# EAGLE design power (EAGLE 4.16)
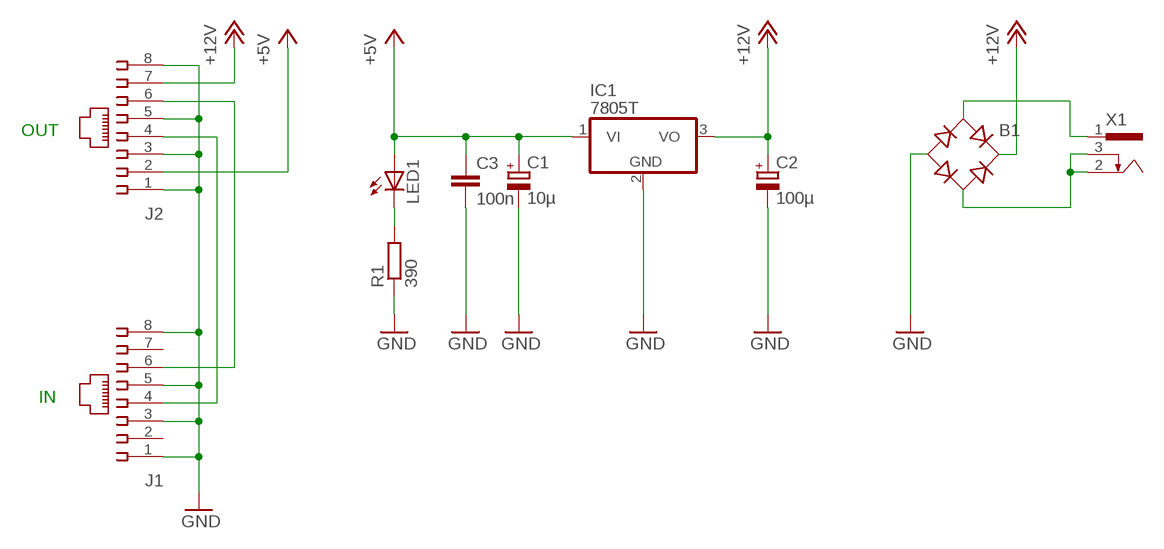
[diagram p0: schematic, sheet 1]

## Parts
B1  RB1A  [RB1A]
C1  10µ  CPOL-EUE2,5-6E  [E2,5-6E]
C2  100µ  CPOL-EUE2,5-6E  [E2,5-6E]
C3  100n  C-EU025-024X044  [C025-024X044]
IC1  7805T  [TO220H]
J1  520243-4  [520243-4]
J2  520243-4  [520243-4]
LED1  LED3MM  [LED3MM]
R1  390  R-EU_0207/7  [0207/7]
X1  733980-62  [733980-62]

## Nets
+5V: C1.+ C3.1 IC1.1(VI) J2.2 LED1.A
+12V: B1.+ C2.+ IC1.3(VO) J2.7
GND: B1.- C1.- C2.- C3.2 IC1.2(GND) J1.1 J1.3 J1.5 J1.8 J2.1 J2.3 J2.5 J2.8 R1.1
N$1: J1.6 J2.6
N$2: LED1.K(C) R1.2
N$3: J1.4 J2.4
N$4: B1.AC1 X1.1
N$5: B1.AC2 X1.2 X1.3
Unconnected: J1.2 J1.7

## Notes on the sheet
- OUT
- IN

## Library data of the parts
B1 = rectifier:RB1A: RECTIFIER 1 A
C1 C2 = rcl:CPOL-EU: POLARIZED CAPACITOR, European symbol
C3 = rcl:C-EU: CAPACITOR, European symbol
IC1 = linear:78*: Positive VOLTAGE REGULATOR Source: http://cache.national.com/ds/LM/LM78L05.pdf http://www.fairchildsemi.com/ds/LM/LM7805.pdf
J1 J2 = con-amp:520243-4: AMP connector
LED1 = led:LED: LED
R1 = rcl:R-EU_: RESISTOR, European symbol
X1 = con-conrad:73398?: FEMALE PRINT CONNECTOR Niedervolt-Steckverbinder Distributor Conrad

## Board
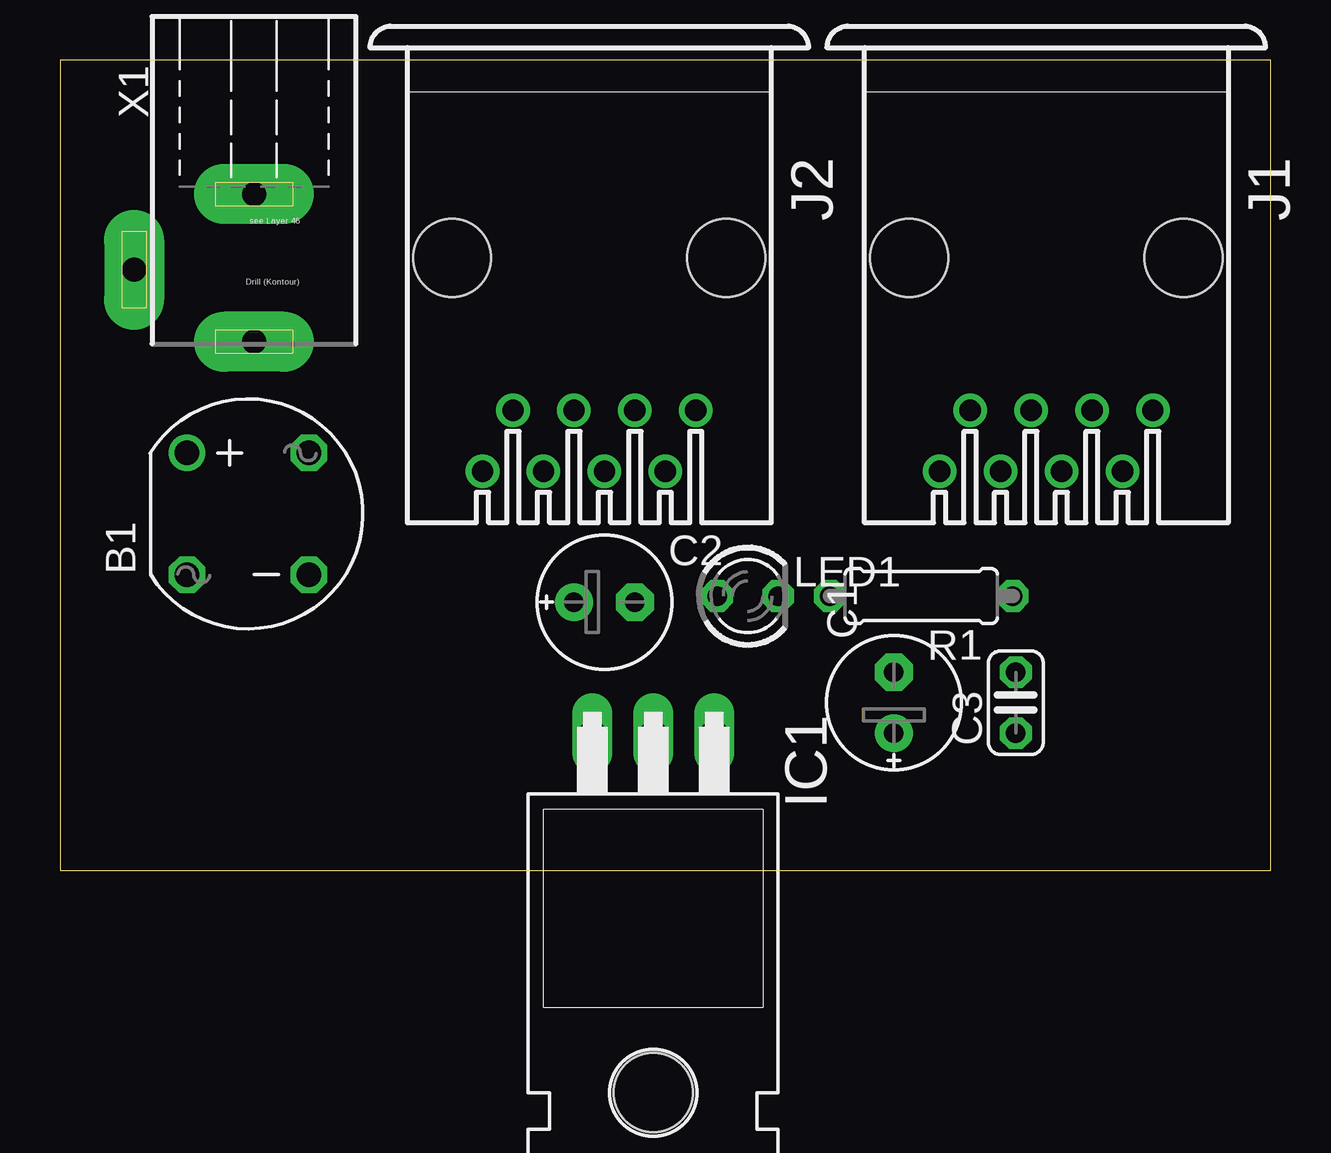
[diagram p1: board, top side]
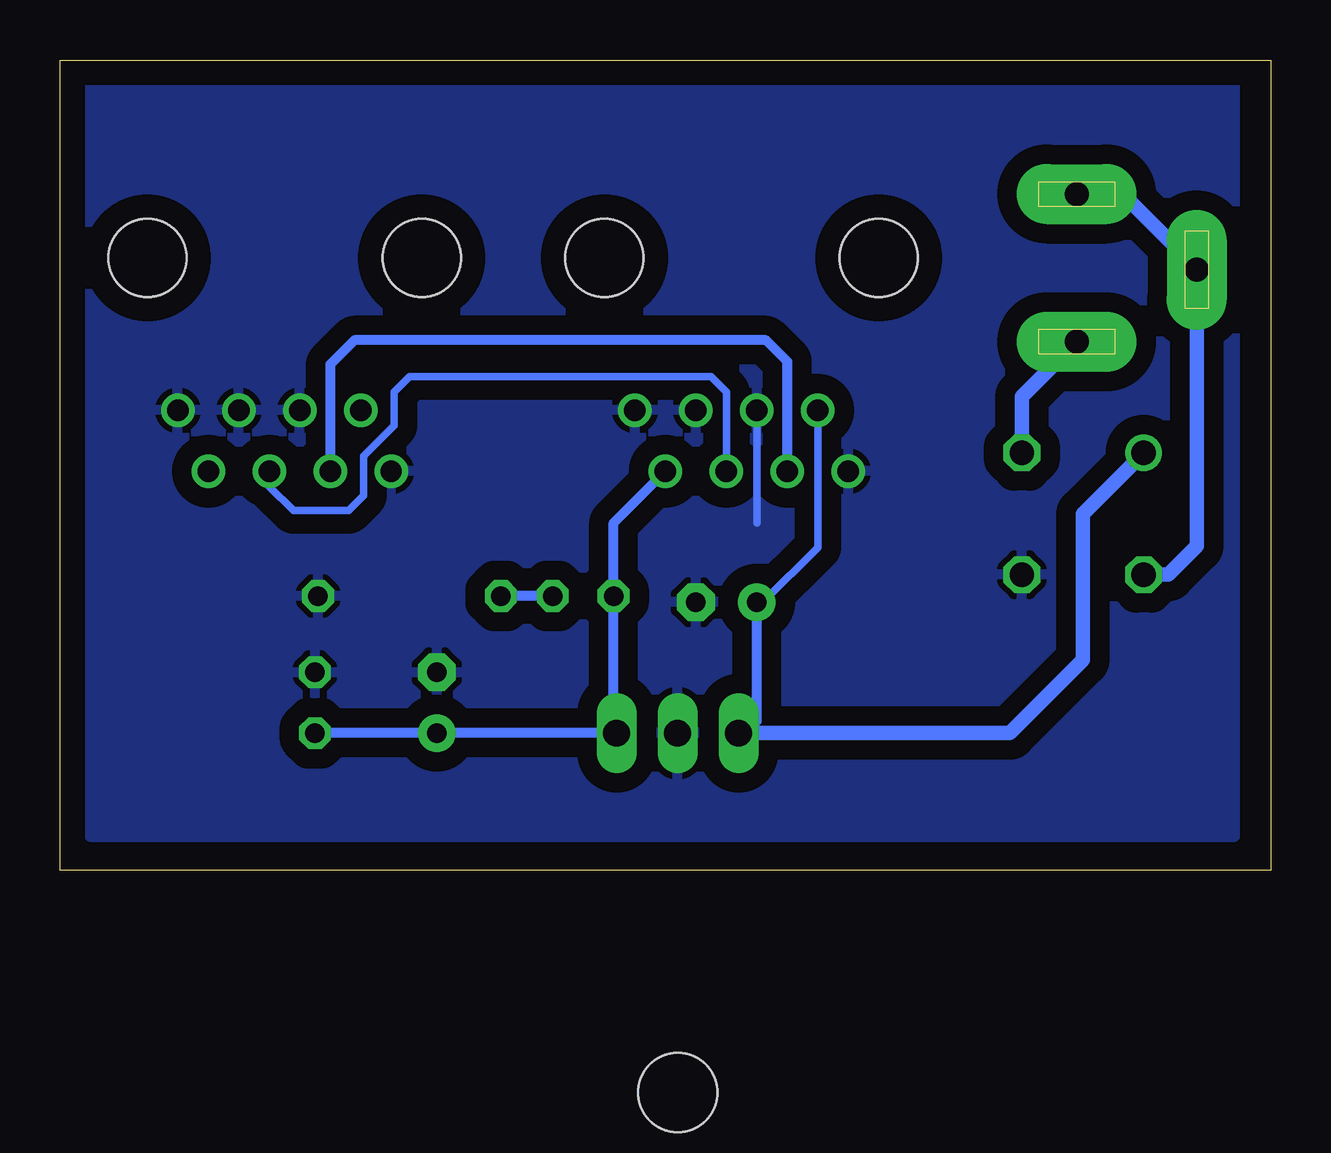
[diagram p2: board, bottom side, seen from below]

Size 50.47 x 33.77 mm. Coordinates in mm from the lower left corner, seen from the top.
Outline: 0,0 50.47,0 50.47,33.77 0,33.77 0,0
Copper layers (1*16): Top 0.035mm / dielectric 1.5mm / Bottom 0.035mm
Design rules "default": minimum track width 10mil, minimum drill 24mil, track to track 8mil, track to pad 8mil, pad to pad 8mil, via to via 8mil, smd to smd 8mil, copper to edge 40mil, drill to drill 8mil, minimum pad ring 10mil, minimum via ring 8mil, stop-mask expansion 4mil, vias tented up to drill 0mil, thermal gap 10mil

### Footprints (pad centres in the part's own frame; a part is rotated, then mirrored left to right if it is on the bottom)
RB1A = drill 1.016 round: + -2.54,2.54 | drill 1.016 octagon: - 2.54,-2.54; AC1 2.54,2.54; AC2 -2.54,-2.54
E2,5-6E = drill 0.813 pad 1.575 round: + -1.27,0 | drill 0.813 pad 1.575 octagon: - 1.27,0
C025-024X044 = drill 0.813 octagon: 1 -1.27,0; 2 1.27,0
TO220H = drill 1.118 long: 1 -2.54,-10.16; 2 0,-10.16; 3 2.54,-10.16 | hole 3.302: 0,4.826
520243-4 = drill 0.889 round: 1 -4.445,6.35; 2 -3.175,8.89; 3 -1.905,6.35; 4 -0.635,8.89; 5 0.635,6.35; 6 1.905,8.89; 7 3.175,6.35; 8 4.445,8.89 | hole 3.251: -5.715,0; 5.715,0
LED3MM = drill 0.813 octagon: A -1.27,0; K 1.27,0
0207/7 = drill 0.813 octagon: 1 -3.81,0; 2 3.81,0
733980-62 = drill 1 pad 2.5 long: 1 0,8.57; 2 0,2.42; 3 5,5.57

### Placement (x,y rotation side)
B1  7.84,14.85 0 top
C1  34.76,6.98 90 top
C2  22.7,11.17 0 top
C3  39.84,6.98 90 top
IC1  24.73,-4.45 180 top
J1  41.11,25.52 180 top
J2  22.06,25.52 180 top
LED1  28.66,11.43 0 top
R1  35.9,11.43 180 top
X1  8.09,30.6 180 top

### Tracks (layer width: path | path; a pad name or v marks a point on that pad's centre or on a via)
+5V
  Bottom 0.406: C1.+ 34.89,5.71 | C1.+ IC1.1 27.01,5.71 27.39,6.09 LED1.A 27.39,14.47 J2.2 | C3.1 39.84,5.58 39.71,5.71 C1.+
+12V
  Bottom 0.305: C2.+ 21.17,11.17 18.89,13.46 J2.7
  Bottom 0.406: IC1.3 21.93,5.71 21.43,6.22 C2.+
  Bottom 0.61: B1.+ 7.84,14.85 7.84,8.76 10.88,5.71 IC1.3 22.31,5.71
GND
  Bottom 0.305: 21.43,14.47 J2.5
  pour Bottom (isolate 0.813): 1.49,33.14 49.24,33.14 49.24,1.39 1.49,1.39
N$1
  Bottom 0.406: J2.6 20.15,21.2 21.04,22.09 38.19,22.09 39.2,21.08 J1.6
N$2
  Bottom 0.406: R1.2 32.09,11.3 31.97,11.43 LED1.K
N$3
  Bottom 0.305: J2.4 22.7,19.93 23.33,20.57 35.9,20.57 36.54,19.93 36.54,18.54 37.81,17.27 37.81,15.62 38.44,14.98 40.73,14.98 41.75,16 J1.4
N$4
  Bottom 0.61: X1.1 10.38,19.75 B1.AC1
N$5
  Bottom 0.61: 3.03,25.03 3.01,25.01 | 3.03,25.03 X1.3 3.09,13.5 4.28,12.31 B1.AC2 | X1.2 6.18,28.18 3.03,25.03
